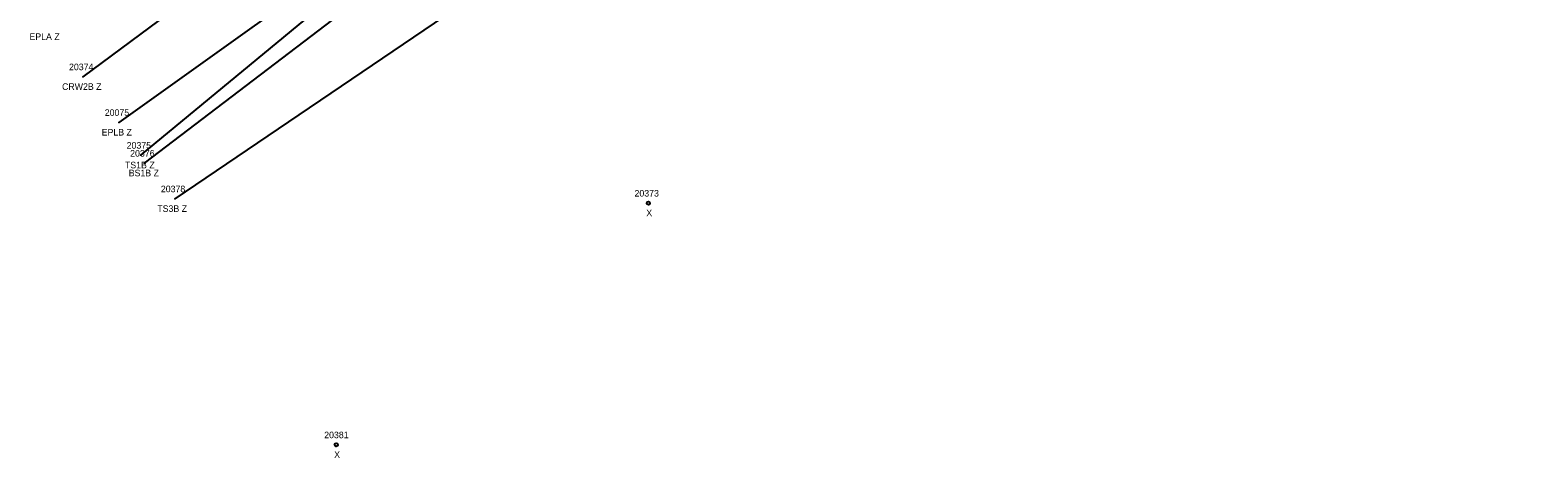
# Model space of a CAD drawing. Extents: x 1813127 to 1818290, y 1178171 to 1179900.
# Drawn here: x 1813574.7 to 1813804.5, y 1178408.6 to 1178473.8 of the extents above; entities that cross this region are included whole.
import ezdxf

# ---------------------------------------------------------------- set-up
doc = ezdxf.new("R2010")
doc.units = 0
for name, color, linetype in [('RD_DTM_BkLn1', 7, 'Continuous'), ('RD_DTM_BkLn2', 7, 'Continuous'), ('RD_EX_Road', 7, 'Continuous'), ('RD_EX_Road_txCode', 7, 'Continuous'), ('RD_SMD_Locator', 7, 'Continuous'), ('RD_SMD_Misc', 7, 'Continuous')]:
    doc.layers.add(name, color=color, linetype=linetype)

msp = doc.modelspace()

# ---------------------------------------------------------------- linework, layer by layer
at = {"layer": 'RD_DTM_BkLn1'}
msp.add_lwpolyline([(1813831.28, 1178643.33), (1813821.11, 1178637.41), (1813809.78, 1178629.12), (1813788.78, 1178614.79), (1813747.67, 1178586.85), (1813706.5, 1178558.14), (1813665.11, 1178528), (1813623.37, 1178496.83), (1813582.75, 1178466.66)], dxfattribs=at)
at = {"layer": 'RD_DTM_BkLn2'}
for points in [[(1813746.03, 1178561.9), (1813743.83, 1178564.42), (1813716.29, 1178544.93), (1813674.06, 1178515.49), (1813631.05, 1178487.38), (1813591.54, 1178454.7)], [(1813744.11, 1178561.57), (1813717.38, 1178543.56), (1813675.31, 1178513.46), (1813633, 1178484.68), (1813592.1, 1178453.49)], [(1813777.22, 1178536.25), (1813747.77, 1178553.49), (1813723.22, 1178536.36), (1813683.91, 1178504.3), (1813639.44, 1178476.94), (1813596.75, 1178448.06)]]:
    msp.add_lwpolyline(points, dxfattribs=at)
at = {"layer": 'RD_EX_Road'}
msp.add_lwpolyline([(1813815.99, 1178618.51), (1813795.14, 1178605.39), (1813756.93, 1178582.36), (1813736.74, 1178567), (1813712.58, 1178549.43), (1813670.71, 1178519.43), (1813630, 1178489.55), (1813588.23, 1178459.7)], dxfattribs=at)
at = {"layer": 'RD_SMD_Locator'}
for centre, radius in [((1813582.75, 1178466.66), 0.001), ((1813588.23, 1178459.7), 0.001), ((1813591.54, 1178454.7), 0.001), ((1813592.1, 1178453.49), 0.001), ((1813596.75, 1178448.06), 0.001), ((1813668.94, 1178447.4), 0.25), ((1813621.36, 1178410.56), 0.25)]:
    msp.add_circle(centre, radius, dxfattribs=at)

# ---------------------------------------------------------------- texts
at = {"layer": 'RD_EX_Road_txCode'}
for s, p in [('EPLA Z', (1813574.6, 1178472.27)), ('20075', (1813586.08, 1178460.7)), ('EPLB Z', (1813585.61, 1178457.7))]:
    msp.add_text(s, height=1, dxfattribs=at).set_placement(p)
at = {"layer": 'RD_SMD_Misc'}
for s, p in [('20374', (1813580.63, 1178467.66)), ('CRW2B Z', (1813579.57, 1178464.66)), ('20375', (1813589.42, 1178455.7)), ('TS1B Z', (1813589.16, 1178452.7)), ('20376', (1813589.95, 1178454.49)), ('BS1B Z', (1813589.73, 1178451.49)), ('20378', (1813594.63, 1178449.06)), ('20373', (1813666.83, 1178448.4)), ('TS3B Z', (1813594.09, 1178446.06)), ('X', (1813668.63, 1178445.4)), ('20381', (1813619.53, 1178411.56)), ('X', (1813621.05, 1178408.56))]:
    msp.add_text(s, height=1, dxfattribs=at).set_placement(p)

doc.saveas('drawing.dxf')
